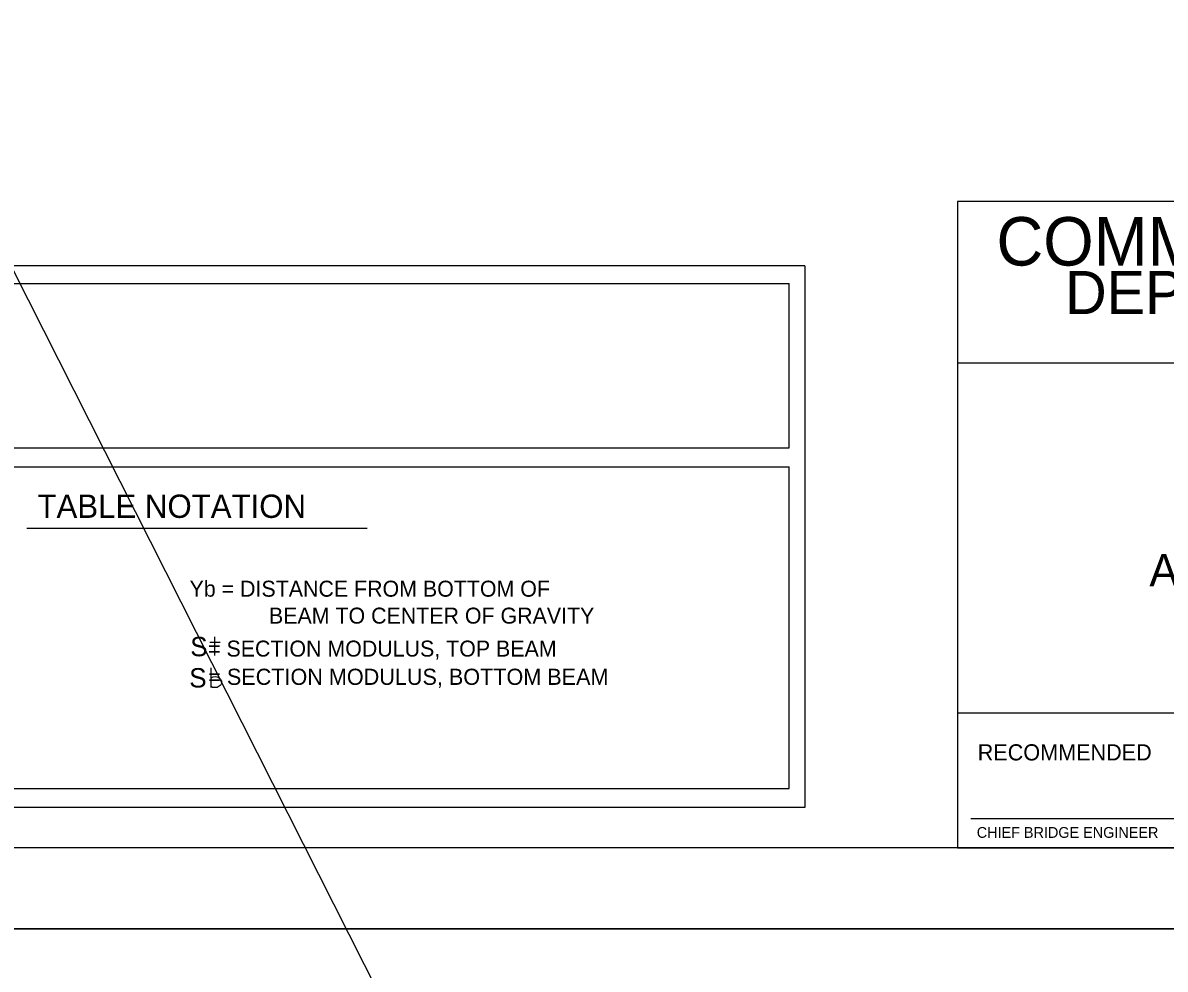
# Model space of a CAD drawing. Extents: x 635698 to 639877, y 296617 to 300175.
# Drawn here: x 636957.9 to 637170, y 298869.3 to 299044.9 of the extents above; entities that cross this region are included whole.
import ezdxf

# ---------------------------------------------------------------- set-up
doc = ezdxf.new("R2010")
doc.units = 0
for name, color, linetype in [('1', 7, 'Continuous'), ('2', 7, 'Continuous'), ('PLT-BNDY', 7, 'Continuous')]:
    doc.layers.add(name, color=color, linetype=linetype)

msp = doc.modelspace()

# ---------------------------------------------------------------- linework, layer by layer
at = {"layer": '1'}
msp.add_line((636360.88, 300174.81), (637328.96, 298262.27), dxfattribs=at)
at = {"layer": '2'}
for p, q in [((637331.45, 299011.76), (637131.45, 299011.76)), ((637131.45, 299011.76), (637131.45, 298891.76)), ((637103.08, 298999.83), (636892.96, 298999.83)), ((637103.08, 298999.83), (637103.08, 298899.29)), ((636895.33, 298996.58), (637100.21, 298996.58)), ((637100.21, 298966.04), (637100.21, 298996.58)), ((637331.45, 298981.76), (637131.45, 298981.76)), ((636895.33, 298966.04), (637100.21, 298966.04)), ((636895.33, 298962.54), (637100.21, 298962.54)), ((637100.21, 298902.79), (637100.21, 298962.54)), ((636958.58, 298951.16), (637021.83, 298951.16)), ((637331.45, 298916.76), (637131.45, 298916.76)), ((636895.33, 298902.79), (637100.21, 298902.79)), ((637103.08, 298899.29), (636892.96, 298899.29)), ((637133.95, 298897.26), (637201.18, 298897.26)), ((637331.45, 298891.76), (636545.45, 298891.76)), ((637131.45, 298891.76), (637331.45, 298891.76))]:
    msp.add_line(p, q, dxfattribs=at)
for points in [[(636993.54, 298927.47), (636993.54, 298930.93)], [(636994.5, 298929.88), (636992.6, 298929.88)], [(636992.82, 298921.52), (636992.82, 298925.22)], [(636992.85, 298923.35), (636993.22, 298923.56), (636993.58, 298923.6), (636993.91, 298923.56), (636994.2, 298923.42), (636994.39, 298923.31), (636994.57, 298923.1), (636994.66, 298922.92), (636994.75, 298922.76), (636994.75, 298922.32), (636994.62, 298922.07), (636994.5, 298921.93), (636994.16, 298921.68), (636993.93, 298921.56), (636993.58, 298921.52), (636993.12, 298921.56), (636992.85, 298921.75)]]:
    msp.add_lwpolyline(points, dxfattribs=at)
at = {"layer": 'PLT-BNDY'}
for points in [[(636505.45, 299470.76), (637346.45, 299470.76), (637346.45, 298876.76), (636505.45, 298876.76)], [(636505.45, 298876.76), (637346.45, 298876.76), (637346.45, 298282.76), (636505.45, 298282.76)]]:
    msp.add_lwpolyline(points, close=True, dxfattribs=at)

# ---------------------------------------------------------------- texts
at = {"layer": '2'}
for s, height, p in [('COMMONWEALTH OF PENNSYLVANIA', 9, (637138.7, 298999.89)), ('DEPARTMENT OF TRANSPORTATION', 8.0002, (637151.45, 298990.89)), ('TABLE NOTATION', 4.3312, (636960.58, 298953.04)), ('AND SECTION PROPERTIES', 6, (637167.1, 298940.32)), ('Yb = DISTANCE FROM BOTTOM OF', 2.9685, (636988.83, 298938.41)), ('BEAM TO CENTER OF GRAVITY', 2.9685, (637003.58, 298933.41)), ('S', 3.6, (636988.96, 298927.35)), ('   = SECTION MODULUS, TOP BEAM', 2.9685, (636988.96, 298927.29)), ('S', 3.6, (636988.77, 298921.55)), ('   = SECTION MODULUS, BOTTOM BEAM', 3, (636988.96, 298922.04)), ('CHIEF BRIDGE ENGINEER', 2.0002, (637135.04, 298893.64))]:
    msp.add_text(s, height=height, dxfattribs=at).set_placement(p)
msp.add_text('RECOMMENDED', height=3, rotation=360, dxfattribs=at).set_placement((637135.22, 298908.01))

doc.saveas('drawing.dxf')
